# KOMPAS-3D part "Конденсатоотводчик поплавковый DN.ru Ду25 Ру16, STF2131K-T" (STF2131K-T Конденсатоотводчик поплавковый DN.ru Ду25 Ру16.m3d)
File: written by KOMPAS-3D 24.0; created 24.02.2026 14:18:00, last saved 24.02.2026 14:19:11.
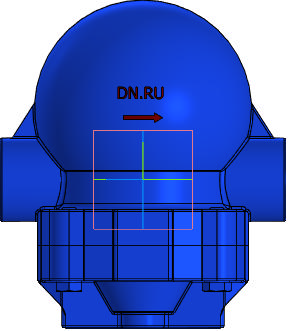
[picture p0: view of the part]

Document properties: Автор: R2D2; Полное имя файла: STF2131K-T Конденсатоотводчик поплавковый DN.ru Ду25 Ру16 (2d).cdw

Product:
- Part/product: Конденсатоотводчик поплавковый DN.ru Ду25 Ру16  | designation STF2131K-T
    Масса: 4
    Раздел спецификации: Прочие изделия
    Форматы листов документа: A2
    Примечание: D150-00321
    additional columns: D150-00321

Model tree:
1. Операция без истории:1

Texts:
  STF2131K-T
